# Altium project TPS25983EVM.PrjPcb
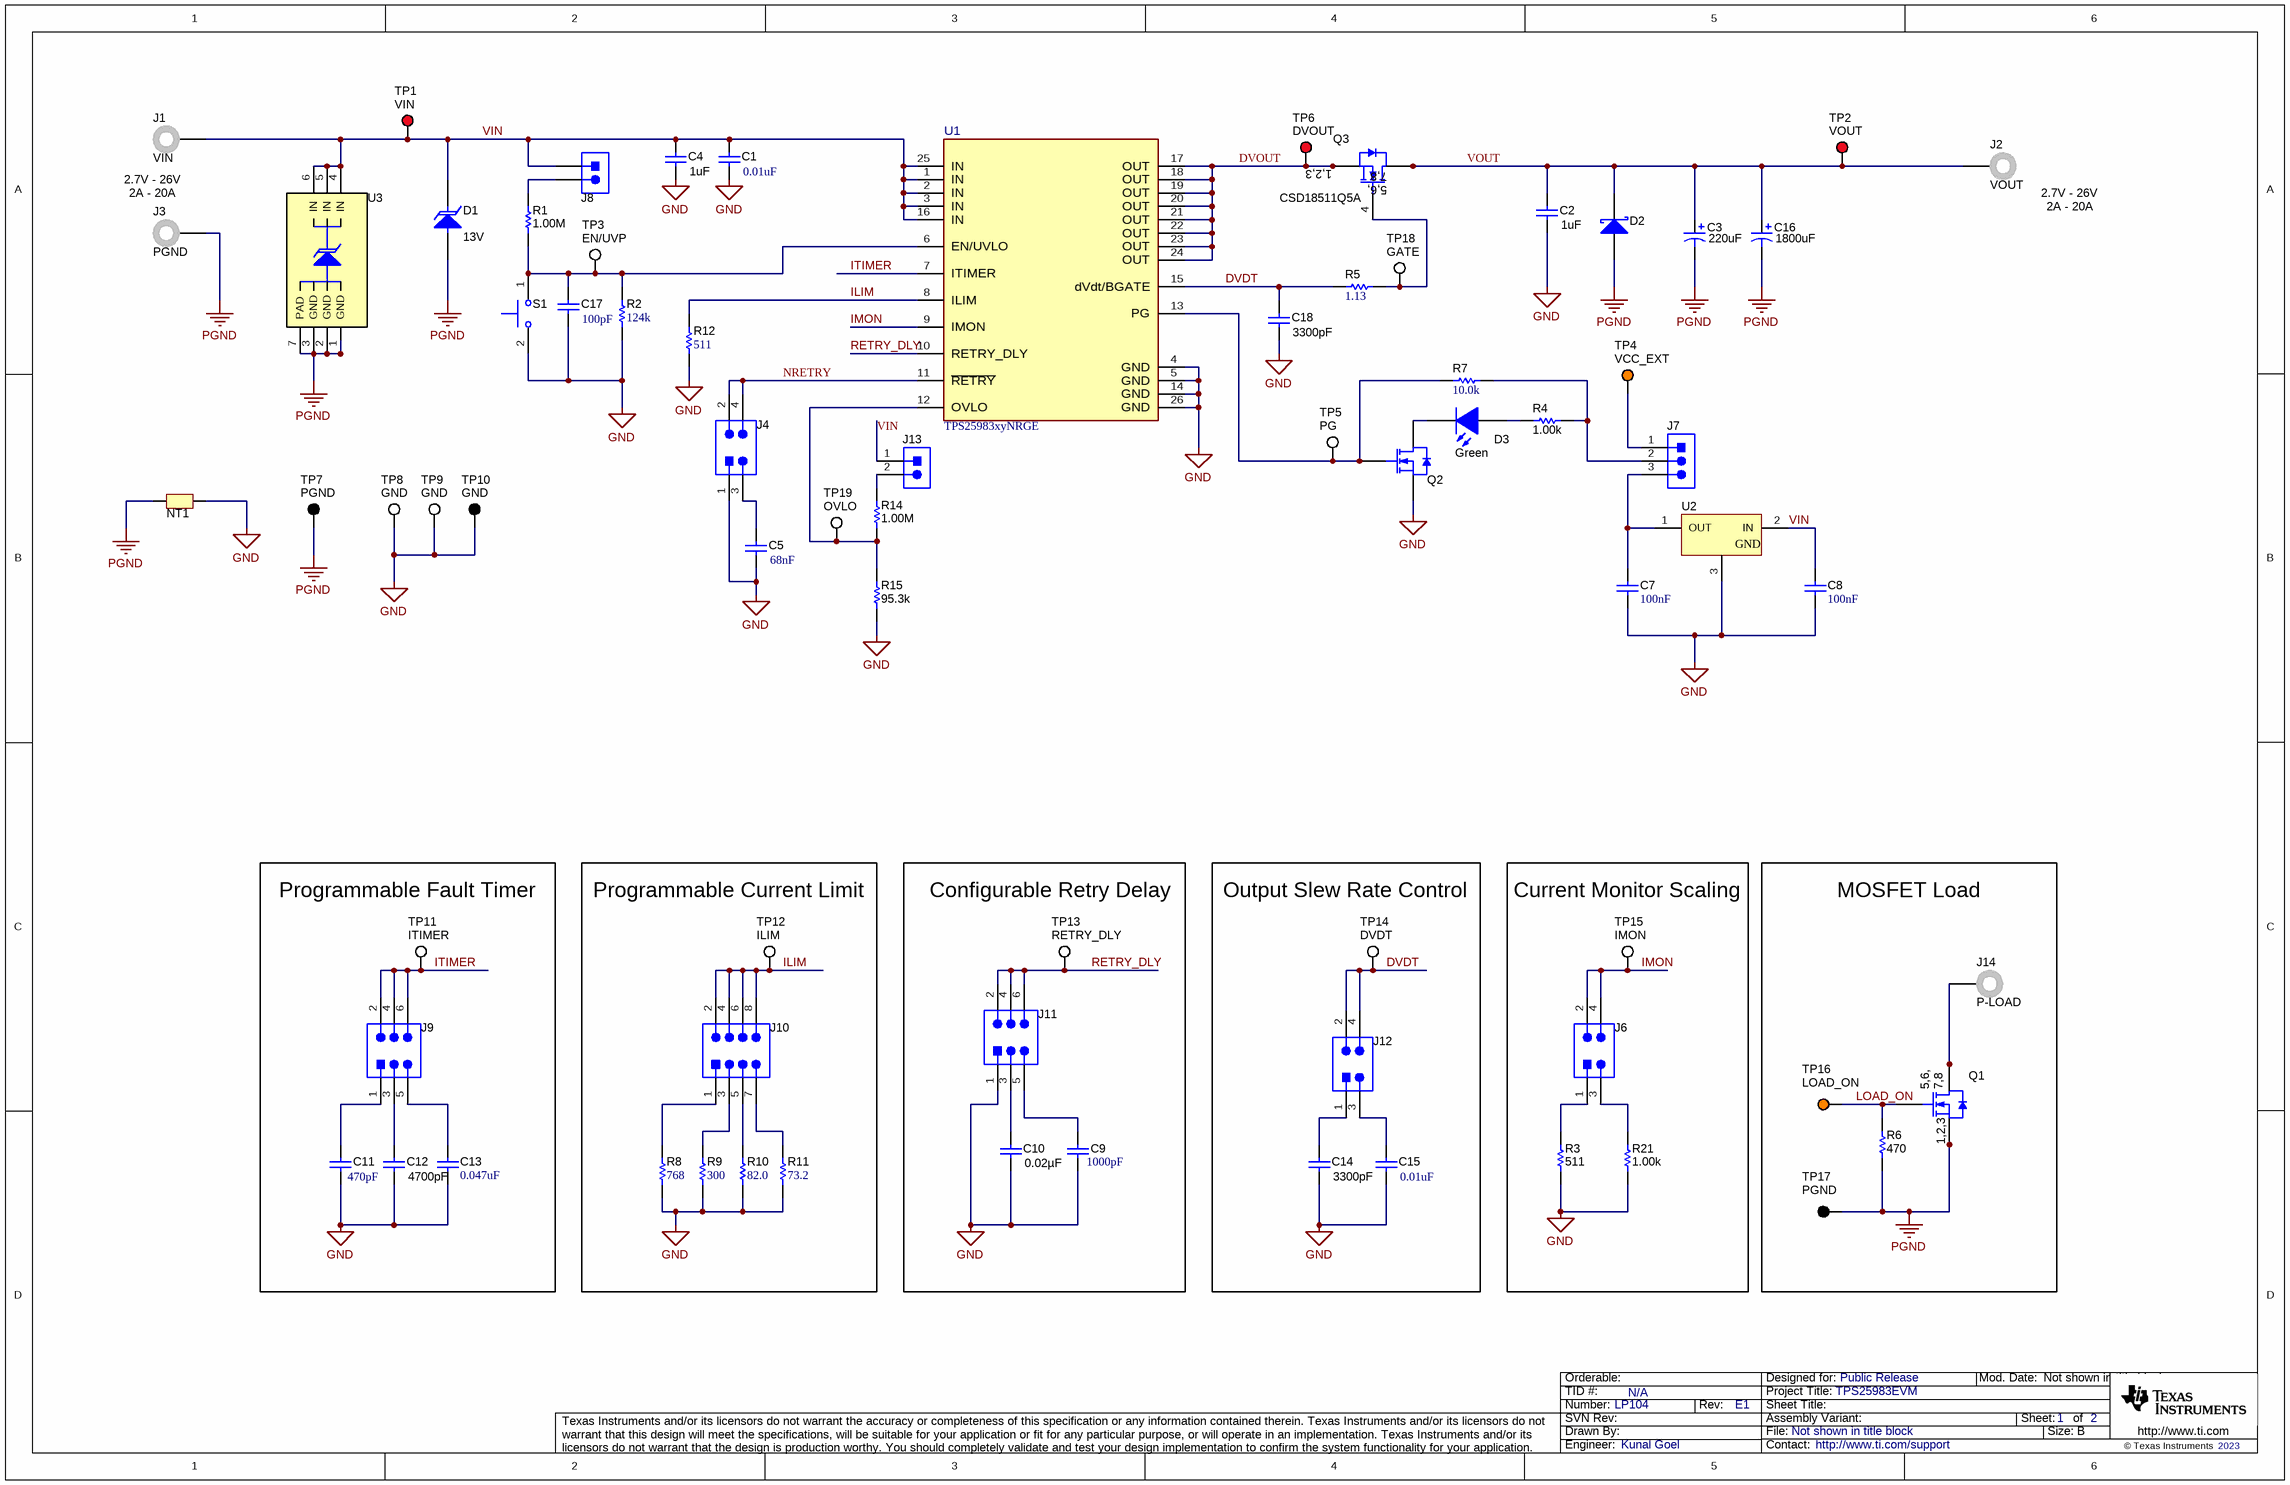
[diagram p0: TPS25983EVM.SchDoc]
CopyrightYear: 2023; PCB_Layout: Pactron; PCB_Rev: E1; PRJ_Customer: Public Release; PRJ_Engineer: Kunal Goel; PRJ_Number: LP104; PRJ_Title: TPS25983EVM; SCH_Rev: E1; TechSupport: http://www.ti.com/support; TID: N/A
2 sheets, 100 parts. Net scope: global (net labels, ports and power ports of the same name join across sheets).
Board file: TPS25983EVM_060523-1m.PcbDoc
Sheets:
  TPS25983EVM.SchDoc
  TPS25983EVM_Hardware.SchDoc

## Sheet TPS25983EVM.SchDoc
size 431 x 279 mm; Date: Not shown in title block; ApprovedBy: Not shown in title block; CheckedBy: Not shown in title block; Author: Not shown in title block; CompanyName: Not shown in title block; Engineer: Not shown in title block; Organization: Not shown in title block; Address1: Not shown in title block; Address2: Not shown in title block; Address3: Not shown in title block; Address4: Not shown in title block; DocumentNumber: 1; Revision: Use project parameter SCH_Rev; SheetNumber: 1; SheetTotal: 2

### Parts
C1  ValueDisplayed: 0.01uF  [0603]  (hidden comment: C0603C103J5RACTU)
C2  ValueDisplayed: 1uF  [0805_HV]  (hidden comment: GMK212B7105KG-T)
C3  ValueDisplayed: 220uF  [SM_RADIAL_G]  (hidden comment: EEE-FC1V221P)
C4  ValueDisplayed: 1uF  [0805_HV]  (hidden comment: GMK212B7105KG-T)
C5  Cap_F: 68nF  [0603]  (hidden comment: 885012206070)
C7  Cap_F: 100nF  [0603]  (hidden comment: 06035C104KAT2A)
C8  Cap_F: 100nF  [0603]  (hidden comment: 06035C104KAT2A)
C9  ValueDisplayed: 1000pF  [0603]  (hidden comment: C0603C102K3GACTU)
C10  ValueDisplayed: 0.02µF  [0805_HV]  (hidden comment: GRM21B5C1H203JA01L)
C11  ValueDisplayed: 470pF  [0603]  (hidden comment: 06035A471JAT2A)
C12  ValueDisplayed: 4700pF  [0603]  (hidden comment: C0603C472J5RACTU)
C13  ValueDisplayed: 0.047uF  [0603]  (hidden comment: C1608X7S2A473K080AB)
C14  ValueDisplayed: 3300pF  [0603]  (hidden comment: C0603X332K5RACTU)
C15  ValueDisplayed: 0.01uF  [0603]  (hidden comment: GRM1885C1H103JA01D)
C16  ValueDisplayed: 1800uF  [PW_1800x2000]  (hidden comment: UPW1V182MHD6)
C17  ValueDisplayed: 100pF  [0603]  (hidden comment: 885012006057)
C18  ValueDisplayed: 3300pF  [0603]  (hidden comment: C0603X332K5RACTU)
D1  value 13V  [SMC]  (hidden comment: SMCJ13A-TR)
D2  B530C-13-F  [SMC]  (value not drawn)
D3  value Green  [LTST-C170KGKT_Green]  (hidden comment: LTST-C170KGKT)
J1  VIN  [Keystone575-8]
J2  VOUT  [Keystone575-8]
J3  PGND  [Keystone575-8]
J4  PEC02DAAN  [Sullins_PEC02DAAN]  (value not drawn)
J6  PEC02DAAN  [Sullins_PEC02DAAN]  (value not drawn)
J7  Header_3x1_Launchpad  [CONN_PEC03SAAN]  (value not drawn)
J8  Header_2x1  [Sullins_PBC02SAAN]  (value not drawn)
J9  PEC03DAAN  [SULLINS_PEC03DAAN]  (value not drawn)
J10  PEC04DAAN  [CONN_PEC04DAAN]  (value not drawn)
J11  PEC03DAAN  [SULLINS_PEC03DAAN]  (value not drawn)
J12  PEC02DAAN  [Sullins_PEC02DAAN]  (value not drawn)
J13  PEC02SAAN  [CONN_PEC02SAAN]  (value not drawn)
J14  P-LOAD  [Keystone575-8]
NT1  Net-Tie  [NetTie_0603]  (value not drawn)  (net tie, no BOM)
Q1  CSD17573Q5B  [DNK0008A]  (value not drawn)
Q2  2N7002  [SOT-23]  (value not drawn)
Q3  CSD18511Q5A  [DQJ0008A]
R1  ValueDisplayed: 1.00M  [0603]  (hidden comment: RC0603FR-071ML)
R2  ValueDisplayed: 124k  [0603]  (hidden comment: CRCW0603124KFKEA)
R3  ValueDisplayed: 511  [0603]  (hidden comment: RC0603FR-07511RL)
R4  ValueDisplayed: 1.00k  [0603]  (hidden comment: RC0603FR-071KL)
R5  ValueDisplayed: 1.13  [0805_HV]  (hidden comment: CRCW08051R13FKEA)
R6  ValueDisplayed: 470  [0603]  (hidden comment: RC0603FR-07470RL)
R7  ValueDisplayed: 10.0k  [0603]  (hidden comment: RG1608P-103-B-T5)
R8  ValueDisplayed: 768  [0603]  (hidden comment: RC0603FR-07768RL)
R9  ValueDisplayed: 300  [0603]  (hidden comment: RC0603FR-07300RL)
R10  ValueDisplayed: 82.0  [0603]  (hidden comment: RC0603FR-0782RL)
R11  ValueDisplayed: 73.2  [0603]  (hidden comment: RC0603FR-0773R2L)
R12  ValueDisplayed: 511  [0603]  (hidden comment: RT0603BRD07511RL)
R14  ValueDisplayed: 1.00M  [0603]  (hidden comment: RC0603FR-071ML)
R15  ValueDisplayed: 95.3k  [0603]  (hidden comment: RC0603FR-0795K3L)
R21  ValueDisplayed: 1.00k  [0603]  (hidden comment: RC0603FR-071KL)
S1  SKRKAEE020  [SW_SKRKAE]  (value not drawn)
TP1  VIN  [Keystone5010]
TP2  VOUT  [Keystone5010]
TP3  EN/UVP  [Keystone5012]
TP4  VCC_EXT  [Keystone5013]
TP5  PG  [Keystone5012]
TP6  DVOUT  [Keystone5010]
TP7  PGND  [Keystone5011]
TP8  GND  [Testpoint_Keystone_Compact]
TP9  GND  [Testpoint_Keystone_Compact]
TP10  GND  [Keystone5011]
TP11  ITIMER  [Keystone5012]
TP12  ILIM  [Keystone5012]
TP13  RETRY_DLY  [Keystone5012]
TP14  DVDT  [Keystone5012]
TP15  IMON  [Keystone5012]
TP16  LOAD_ON  [Keystone5013]
TP17  PGND  [Keystone5011]
TP18  GATE  [Keystone5012]
TP19  OVLO  [Keystone5012]
U1  TPS25983xyNRGE  [RGE0024M-MFG]
U2  LM3480IM3-3.3/NOPB  [DBZ0003A_N]  (value not drawn)
U3  TVS2200DRVR  [DRV0006A]  (value not drawn)

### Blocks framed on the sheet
Programmable Fault Timer: C11-C13 J9 TP11
Programmable Current Limit: J10 R8-R11 TP12
Configurable Retry Delay: C9 C10 J11 TP13
Output Slew Rate Control: C14 C15 J12 TP14
Current Monitor Scaling: J6 R3 R21 TP15
MOSFET Load: J14 Q1 R6 TP16 TP17

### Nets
GND: C1.2 C2.2 C4.2 C5.2 C7.2 C8.2 C9.2 C10.2 C11.2 C12.2 C13.2 C14.2 C15.2 C17.2 C18.2 J4.1 J11.1 NT1.1 Q2.2(S) R2.1 R3.1 R8.1 R9.1 R10.1 R11.1 R12.2 R15.1 R21.1 S1.2 TP8.1 TP9.1 TP10.1 U1.4(GND) U1.5(GND) U1.14(GND) U1.26(GND) U2.3(GND)
PGND: C3.2(-) C16.2(-) D1.2(A) D2.2(A) J3.1 NT1.2 Q1.1(S) Q1.2(S) Q1.3(S) R6.1 TP7.1 TP17.1 U3.1(GND) U3.2(GND) U3.3(GND) U3.7(PAD)
DVDT: C18.1 J12.2 J12.4 R5.1 TP14.1 U1.15(dVdt/BGATE)
DVOUT: Q3.1(S) Q3.2(S) Q3.3(S) TP6.1 U1.17(OUT) U1.18(OUT) U1.19(OUT) U1.20(OUT) U1.21(OUT) U1.22(OUT) U1.23(OUT) U1.24(OUT)
ILIM: J10.2 J10.4 J10.6 J10.8 R12.1 TP12.1 U1.8(ILIM)
IMON: J6.2 J6.4 TP15.1 U1.9(IMON)
ITIMER: J9.2 J9.4 J9.6 TP11.1 U1.7(ITIMER)
LOAD_ON: Q1.4(G) R6.2 TP16.1
NRETRY: J4.2 J4.4 U1.11(~{RETRY})
RETRY_DLY: J11.2 J11.4 J11.6 TP13.1 U1.10(RETRY_DLY)
VIN: C1.1 C4.1 C8.1 D1.1(K) J1.1 J8.1 J13.1 TP1.1 U1.1(IN) U1.2(IN) U1.3(IN) U1.16(IN) U1.25(IN) U2.2(IN) U3.4(IN) U3.5(IN) U3.6(IN)
VOUT: C2.1 C3.1(+) C16.1(+) D2.1(K) J2.1 Q3.5(D) Q3.6(D) Q3.7(D) Q3.8(D) Q3.9(D) TP2.1
NetC5_1: C5.1 J4.3
NetC7_1: C7.1 J7.3 U2.1(OUT)
NetC9_1: C9.1 J11.5
NetC10_1: C10.1 J11.3
NetC11_1: C11.1 J9.1
NetC12_1: C12.1 J9.3
NetC13_1: C13.1 J9.5
NetC14_1: C14.1 J12.1
NetC15_1: C15.1 J12.3
NetC17_1: C17.1 R1.1 R2.2 S1.1 TP3.1 U1.6(EN/UVLO)
NetD3_1: D3.1(A) R4.2
NetD3_2: D3.2(K) Q2.3(D)
NetJ6_1: J6.1 R3.2
NetJ6_3: J6.3 R21.2
NetJ7_1: J7.1 TP4.1
NetJ7_2: J7.2 R4.1 R7.2
NetJ8_2: J8.2 R1.2
NetJ10_1: J10.1 R8.2
NetJ10_3: J10.3 R9.2
NetJ10_5: J10.5 R10.2
NetJ10_7: J10.7 R11.2
NetJ13_2: J13.2 R14.2
NetJ14_1: J14.1 Q1.5(D) Q1.6(D) Q1.7(D) Q1.8(D) Q1.9(D)
NetQ2_1: Q2.1(G) R7.1 TP5.1 U1.13(PG)
NetQ3_4: Q3.4(G) R5.2 TP18.1
NetR14_1: R14.1 R15.2 TP19.1 U1.12(OVLO)

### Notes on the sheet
- 2.7V - 26V
- 2A - 20A

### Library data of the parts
C1 = CMP-0006850-4: CAP, CERM, 0.01 uF, 50 V, +/- 5%, X7R, 0603; Manufacturer: Kemet; TaMin_C: -55°C; Polarized: N; SizeAreaWB_mm2: 4.68; Value1: Unknown; U/M: EA; Value: 0.01uF; TaMax_C: 125°C; SizeZ_mm: 1; SizeX_mm: 1.6; SizeY_mm: 0.8; Value2: 50V; SizeArea_mm2: 1.28; Cap_F: 10nF; AEC Category: Q200
C2 C4 = CMP-0008024-2: CAP, CERM, 1 uF, 35 V, +/- 10%, X7R, 0805; Manufacturer: Taiyo Yuden; TaMin_C: -55°C; Polarized: N; SizeAreaWB_mm2: 6.75; Value1: Unknown; U/M: EA; Value: 1uF; TaMax_C: 125°C; SizeZ_mm: 1.45; SizeX_mm: 2; SizeY_mm: 1.25; Cap_Case: 0805; Value2: 35V; SizeArea_mm2: 2.5; CompType: Capacitor; Cap_F: 1µF; AEC Category: Q200
C3 = CMP-0010667-1: CAP, AL, 220 uF, 35 V, +/- 20%, 0.15 ohm, SMD; Manufacturer: Panasonic; TaMin_C: -40°C; ESR_ohm: 1.5d; Polarized: Y; SizeAreaWB_mm2: 172.2; U/M: EA; Value: 220uF; TaMax_C: 105°C; SizeZ_mm: 10.2; SizeX_mm: 12; SizeY_mm: 10.3; Cap_Case: G; Value2: 35V; SizeArea_mm2: 123.6; CompType: Capacitor; Cap_F: 220µF; IRMS_A: 6.7dA; AEC Category: Q200
C5 = CMP-0750069-1: CAP, CERM, 0.068 µF, 25 V,+/- 10%, X7R, 0603; Manufacturer: Wurth Elektronik; SizeAreaWB_mm2: 4.68; U/M: EA; SizeArea_mm2: 1.28; TaMin_C: -55°C; Value: 0.068uF; SizeY_mm: 0.8; SizeX_mm: 1.6; AEC Category: Q200; VDC_V: 25V; AEC Qualified: N; SizeZ_mm: 1; TaMax_C: 125°C
C7 C8 = CMP-0006802-4: CAP, CERM, 0.1 uF, 50 V, +/- 10%, X7R, 0603; Manufacturer: AVX; TaMin_C: -55°C; Polarized: N; SizeAreaWB_mm2: 4.68; Value1: Unknown; U/M: EA; Value: 0.1uF; TaMax_C: 125°C; SizeZ_mm: 1; SizeX_mm: 1.6; SizeY_mm: 0.8; Value2: 50V; SizeArea_mm2: 1.28; AEC Category: Q200
C9 = CMP-0006846-4: CAP, CERM, 1000 pF, 25 V, +/- 10%, C0G/NP0, 0603; Manufacturer: Kemet; TaMin_C: -55°C; ESR_ohm: 0; Polarized: N; SizeAreaWB_mm2: 4.68; Value1: 0 ohm; U/M: EA; Value: 1000pF; TaMax_C: 125°C; SizeZ_mm: 1; SizeX_mm: 1.6; SizeY_mm: 0.8; Value2: 25V; SizeArea_mm2: 1.28; Cap_F: 1nF; IRMS_A: 0A; AEC Category: Q200
C10 = CMP-0080095-1: CAP, CERM, 0.02 µF, 50 V,+/- 5%, C0G/NP0, 0805; Manufacturer: MuRata; Cap_F: 20nF; SizeAreaWB_mm2: 6.75; SizeArea_mm2: 2.5; AEC Qualified: N; AEC Category: Q200; Value: 0.02uF; TaMax_C: 125°C; SizeZ_mm: 1.45; TaMin_C: -55°C; VDC_V: 50V; SizeY_mm: 1.25; U/M: EA; CompType: Capacitor; SizeX_mm: 2; Cap_Case: 0805
C11 = CMP-0006790-4: CAP, CERM, 470 pF, 50 V, +/- 5%, C0G/NP0, 0603; Manufacturer: AVX; TaMin_C: -55°C; ESR_ohm: 0.063; Polarized: N; SizeAreaWB_mm2: 4.68; Value1: 0.063 ohm; U/M: EA; Value: 470pF; TaMax_C: 125°C; SizeZ_mm: 1; SizeX_mm: 1.6; SizeY_mm: 0.8; Value2: 50V; SizeArea_mm2: 1.28; AEC Category: Q200
C12 = CMP-0006942-4: CAP, CERM, 4700 pF, 50 V, +/- 5%, X7R, 0603; Manufacturer: Kemet; TaMin_C: -55°C; Polarized: N; SizeAreaWB_mm2: 4.68; Value1: Unknown; U/M: EA; Value: 4700pF; TaMax_C: 125°C; SizeZ_mm: 1; SizeX_mm: 1.6; SizeY_mm: 0.8; Value2: 50V; SizeArea_mm2: 1.28; CompType: Capacitor; Cap_F: 4.7nF; AEC Category: Q200
C13 = CMP-0007060-4: CAP, CERM, 0.047 uF, 100 V, +/- 10%, X7S, 0603; Manufacturer: TDK; TaMin_C: -55°C; ESR_ohm: 0.089796; Polarized: N; SizeAreaWB_mm2: 4.68; Value1: 0.089796 ohm; U/M: EA; TaMax_C: 125°C; SizeZ_mm: 1; SizeX_mm: 1.6; SizeY_mm: 0.8; Value2: 100V; SizeArea_mm2: 1.28; CompType: Capacitor; Cap_F: 47nF; IRMS_A: 5.67484dA; AEC Category: Q200
C14 C18 = CMP-0006985-4: CAP, CERM, 3300 pF, 50 V, +/- 10%, X7R, 0603; Manufacturer: Kemet; TaMin_C: -55°C; Polarized: N; SizeAreaWB_mm2: 4.68; Value1: Unknown; U/M: EA; Value: 3300pF; TaMax_C: 125°C; SizeZ_mm: 1; SizeX_mm: 1.6; SizeY_mm: 0.8; Value2: 50V; SizeArea_mm2: 1.28; CompType: Capacitor; Cap_F: 3.3nF; AEC Category: Q200
C15 = CMP-0007174-4: CAP, CERM, 0.01 uF, 50 V, +/- 5%, C0G/NP0, 0603; Manufacturer: MuRata; TaMin_C: -55°C; Polarized: N; SizeAreaWB_mm2: 4.68; Value1: Unknown; U/M: EA; Value: 0.01uF; TaMax_C: 125°C; SizeZ_mm: 1; SizeX_mm: 1.6; SizeY_mm: 0.8; Value2: 50V; SizeArea_mm2: 1.28; Cap_F: 10nF; AEC Category: Q200
C16 = CMP-0010552-2: CAP, AL, 1800 uF, 35 V, +/- 20%, 0.028 ohm, TH; Manufacturer: Nichicon; TaMin_C: -55°C; ESR_ohm: 0.028; Polarized: Y; SizeAreaWB_mm2: 400; U/M: EA; Value: 1800uF; TaMax_C: 105°C; SizeZ_mm: 22; SizeX_mm: 18; Cap_Case: 18x20mm; Value2: 35V; SizeArea_mm2: 324; CompType: Capacitor; AEC Qualified: N; Cap_F: 1.8mF; IRMS_A: 2.49A; AEC Category: Q200
C17 = CMP-0006822-4: CAP, CERM, 100 pF, 50 V, +/- 5%, C0G/NP0, 0603; Manufacturer: Wurth Elektronik; TaMin_C: -55°C; Polarized: N; SizeAreaWB_mm2: 4.68; Value1: Unknown; U/M: EA; Value: 100pF; TaMax_C: 125°C; SizeZ_mm: 1; SizeX_mm: 1.6; SizeY_mm: 0.8; Value2: 50V; SizeArea_mm2: 1.28; CompType: Capacitor; AEC Category: Q200
D1 = CMP-0085423-1: Diode, TVS, Uni, 13 V, 21.5 Vc, 1500 W, 73 A, SMC; Manufacturer: STMicroelectronics; SizeAreaWB_mm2: 83.2686; SizeZ_mm: 2.62; SizeY_mm: 6.22; Ipp: 73A; Ppk: 1.5kW; RJA_CperW: 90; SizeArea_mm2: 50.5686; SizeX_mm: 8.13; Value1: 21.5V; Vbr_Min: 14.4V; AEC Qualified: N; AEC Category: Q101
D2 = CMP-0028430-1: Diode, Schottky, 30 V, 5 A, SMC; Manufacturer: Diodes Inc.; Io_A: 5A; Green_Lifecycle: Active; SizeAreaWB_mm2: 83.2686; Vr_V: 30V; Green_REACh: Passed; TJmax_C: 125°C; U/M: EA; Value: 30V; SizeZ_mm: 2.6; SizeX_mm: 8.13; SizeY_mm: 6.22; Vf_V: 5.5dV; Value2: 0.55V; SizeArea_mm2: 50.5686; AEC Category: Q101; RJC_CperW: 10
D3 = CMP-0002888-1: LED, Green, SMD; Manufacturer: Lite-On; Type: AlInGaP; Vf_V: 2V; Io_A: 20mA; Value1: W; U/M: EA
J1-J3 J14 = CMP-0055166-2: Standard Banana Jack, Uninsulated, 8.9mm; Manufacturer: Keystone; PartNumber: 575-8; CT: TRUE; Green_REACh: Passed; CNHeader: FALSE; Green_Lifecycle: Active
J4 J6 J12 = CMP-0054558-1: Header, 100mil, 2x2, Tin, TH; Manufacturer: Sullins Connector Solutions; CNHeader: TRUE; Green_Lifecycle: Not Set; Green_REACh: Incomplete; CT: FALSE
J7 = CMP-0002338-1: Header, 100mil, 3x1, Tin, TH; PartNumber: PEC03SAAN; Manufacturer: Sullins Connector Solutions; Cert_UL: Y; CNHeader: TRUE; CT: FALSE; Current_A: 3A; Gender: Male; Green_Lifecycle: Not Set; Green_REACh: Incomplete; Pitch_mm: 2.54; Row_Count: 1; Shrouded: N; Voltage_V: 1.8kV
J8 = CMP-0054566-1: Header, 100mil, 2x1, Gold, TH; PartNumber: PBC02SAAN; Manufacturer: Sullins Connector Solutions; Pitch_mm: 2.54; Gender: Male; Shrouded: N; Row_Count: 1; Current_A: 3A; Voltage_V: 1.8kV; Cert_UL: Y; CNHeader: TRUE; CT: FALSE; Green_Lifecycle: Active; Green_REACh: Passed
J9 J11 = CMP-0054552-1: Header, 100mil, 3x2, Tin, TH; Manufacturer: Sullins Connector Solutions; CNHeader: TRUE; Current_A: 3A; Green_Lifecycle: Not Set; Shrouded: N; Gender: Male; Green_REACh: Incomplete; Voltage_V: 1.8kV; Row_Count: 2; RowSpacing_mm: 2.54; CT: FALSE; Cert_UL: Y
J10 = CMP-0054542-1: Header, 100mil, 4x2, Tin, TH; Manufacturer: Sullins Connector Solutions; CNHeader: TRUE; Current_A: 3A; Green_Lifecycle: Not Set; Shrouded: N; Gender: Male; Green_REACh: Incomplete; Voltage_V: 1.8kV; Row_Count: 2; RowSpacing_mm: 2.54; CT: FALSE; Cert_UL: Y
J13 = CMP-0002337-1: Header, 100mil, 2x1, Tin, TH; Manufacturer: Sullins Connector Solutions; CNHeader: TRUE; Current_A: 3A; Green_Lifecycle: Not Set; Shrouded: N; Gender: Male; Green_REACh: Incomplete; Voltage_V: 1.8kV; Row_Count: 1; Pitch_mm: 2.54; CT: FALSE; Cert_UL: Y
NT1 = CMP-0078142-3: Single point connection between nets.
Q1 = CMP-0000586-2: MOSFET, N-CH, 30 V, 100 A, DNK0008A (VSON-CLIP-8); Manufacturer: Texas Instruments; SizeZ_mm: 1; ChType: N; Value2: 49 nC; Value1: 0.0014; VdsMax_V: 30V; SizeX_mm: 6; SizeY_mm: 5; Vgs_V: 20V; Value: 30V; Rdson45_ohm: 1.45m; SizeArea_mm2: 30; AEC Category: Q101; IdsMax_A: 100A; SizeAreaWB_mm2: 56; U/M: EA; QgTyp_nC: 49
Q2 = CMP-0000768-1: MOSFET, N-CH, 60 V, 115 A, SOT-23; Manufacturer: Fairchild Semiconductor; SizeZ_mm: 1.1; ChType: N; VdsMax_V: 60V; SizeX_mm: 2.5; SizeY_mm: 3; Vgs_V: 20V; Value: 60V; SizeArea_mm2: 7.5; AEC Category: Q101; IdsMax_A: 115A; SizeAreaWB_mm2: 14; U/M: EA
Q3 = CMP-0000711-1: MOSFET, N-CH, 40 V, 100 A, DQJ0008A (VSONP-8); Alternate Manufacturer: None; Manufacturer: Texas Instruments; SizeZ_mm: 1.1; ChType: N; Value2: 63 nC; Value1: 0.003; VdsMax_V: 40V; SizeX_mm: 6; SizeY_mm: 4.9; Vgs_V: 20V; Value: 40V; Rdson45_ohm: 3.5m; SizeArea_mm2: 29.4; AEC Category: Q101; IdsMax_A: 100A; SizeAreaWB_mm2: 55.2; U/M: EA; QgTyp_nC: 63
R1 R14 = CMP-0022899-2: RES, 1.00 M, 1%, 0.1 W, 0603; Manufacturer: Yageo America; Power_W: 100mW; TempCo: 200 ppm/C; Value_Code: 1M00; U/M: EA; Value: 1.00Meg; EIA_Code: E96; Res_ohm: 1M; SizeX_mm: 1.6; SizeY_mm: 0.8; SizeZ_mm: 1; Value2: 0.1W; SizeArea_mm2: 1.28; CompType: Resistor; VDC_V: 150V; AEC Category: Q200
R2 = CMP-0022026-4: RES, 124 k, 1%, 0.1 W, AEC-Q200 Grade 0, 0603; Manufacturer: Vishay-Dale; Power_W: 100mW; TempCo: 100 ppm/C; Value: 124k; EIA_Code: E96; SizeX_mm: 1.6; SizeY_mm: 0.8; SizeZ_mm: 1; Value2: 0.1W; SizeArea_mm2: 1.28; AEC Qualified: Y; VDC_V: 75V; AEC Category: Q200; AEC Grade: 0
R3 = CMP-0023165-3: RES, 511, 1%, 0.1 W, 0603; Manufacturer: Yageo America; Power_W: 100mW; TempCo: 200 ppm/C; Value_Code: 511R; U/M: EA; Value: 511; EIA_Code: E96; SizeX_mm: 1.6; SizeY_mm: 0.8; SizeZ_mm: 1; Value2: 0.1W; SizeArea_mm2: 1.28; VDC_V: 150V; AEC Category: Q200
R4 = CMP-0022895-3: RES, 1.00 k, 1%, 0.1 W, 0603; Manufacturer: Yageo America; Power_W: 100mW; TempCo: 200 ppm/C; Value_Code: 1k00; U/M: EA; Value: 1.00k; EIA_Code: E96; Res_ohm: 1k; SizeX_mm: 1.6; SizeY_mm: 0.8; SizeZ_mm: 1; Value2: 0.1W; SizeArea_mm2: 1.28; CompType: Resistor; VDC_V: 150V; AEC Category: Q200
R5 = CMP-0021014-3: RES, 1.13, 1%, 0.125 W, AEC-Q200 Grade 0, 0805; Manufacturer: Vishay-Dale; Power_W: 125mW; TempCo: 100 ppm/C; Value_Code: 1R13; Value: 1.13; EIA_Code: E96; SizeX_mm: 2; SizeY_mm: 1.25; SizeZ_mm: 1.45; Value2: 0.125W; SizeArea_mm2: 2.5; AEC Qualified: Y; VDC_V: 150V; AEC Category: Q200; AEC Grade: 0
R6 = CMP-0023129-3: RES, 470, 1%, 0.1 W, 0603; Manufacturer: Yageo America; Power_W: 100mW; TempCo: 200 ppm/C; Value_Code: 470R; U/M: EA; Value: 470; SizeX_mm: 1.6; SizeY_mm: 0.8; SizeZ_mm: 1; Value2: 0.1W; SizeArea_mm2: 1.28; VDC_V: 150V; AEC Category: Q200
R7 = CMP-0023404-3: RES, 10.0 k, 0.1%, 0.1 W, 0603; Manufacturer: Susumu Co Ltd; Power_W: 100mW; TempCo: 25 ppm/C; Value_Code: 10k0; U/M: EA; Value: 10.0k; EIA_Code: E192; Res_ohm: 10k; SizeX_mm: 1.6; SizeY_mm: 0.8; SizeZ_mm: 1; Value2: 0.1W; SizeArea_mm2: 1.28; CompType: Resistor; VDC_V: 75V; AEC Category: Q200
R8 = CMP-0023270-5: RES, 768, 1%, 0.1 W, 0603; Manufacturer: Yageo; Power_W: 100mW; TempCo: 100 ppm/C; Value_Code: 768R; Value: 768; EIA_Code: E96; SizeX_mm: 1.6; SizeY_mm: 0.8; SizeZ_mm: 1; Value2: 0.1W; SizeArea_mm2: 1.28; AEC Qualified: N; VDC_V: 75V; AEC Category: Q200; SizeAreaWB_mm2: 4.68
R9 = CMP-0023013-5: RES, 300, 1%, 0.1 W, 0603; Manufacturer: Yageo; Power_W: 100mW; TempCo: 100 ppm/C; Value_Code: 300R; Value: 300; SizeX_mm: 1.6; SizeY_mm: 0.8; SizeZ_mm: 1; Value2: 0.1W; SizeArea_mm2: 1.28; AEC Qualified: N; VDC_V: 75V; AEC Category: Q200; SizeAreaWB_mm2: 4.68
R10 = CMP-0023294-5: RES, 82.0, 1%, 0.1 W, 0603; Manufacturer: Yageo; Power_W: 100mW; TempCo: 100 ppm/C; Value_Code: 82R0; Value: 82.0; Res_ohm: 82; SizeX_mm: 1.6; SizeY_mm: 0.8; SizeZ_mm: 1; Value2: 0.1W; SizeArea_mm2: 1.28; AEC Qualified: N; VDC_V: 75V; AEC Category: Q200; SizeAreaWB_mm2: 4.68
R11 = CMP-0023264-5: RES, 73.2, 1%, 0.1 W, 0603; Manufacturer: Yageo; Power_W: 100mW; TempCo: 100 ppm/C; Value_Code: 73R2; Value: 73.2; EIA_Code: E96; SizeX_mm: 1.6; SizeY_mm: 0.8; SizeZ_mm: 1; Value2: 0.1W; SizeArea_mm2: 1.28; AEC Qualified: N; VDC_V: 75V; AEC Category: Q200; SizeAreaWB_mm2: 4.68
R12 = CMP-0024310-2: RES, 511, 0.1%, 0.1 W, 0603; Manufacturer: Yageo America; Power_W: 100mW; TempCo: 25 ppm/C; Value_Code: 511R; U/M: EA; Value: 511; EIA_Code: E192; SizeX_mm: 1.6; SizeY_mm: 0.8; SizeZ_mm: 1; Value2: 0.1W; SizeArea_mm2: 1.28; VDC_V: 75V; AEC Category: Q200
R15 = CMP-0023326-5: RES, 95.3 k, 1%, 0.1 W, 0603; Manufacturer: Yageo; Power_W: 100mW; TempCo: 100 ppm/C; Value_Code: 95k3; Value: 95.3k; EIA_Code: E96; SizeX_mm: 1.6; SizeY_mm: 0.8; SizeZ_mm: 1; Value2: 0.1W; SizeArea_mm2: 1.28; AEC Qualified: N; VDC_V: 75V; AEC Category: Q200; SizeAreaWB_mm2: 4.68
R21 = CMP-0022895-3: RES, 1.00 k, 1%, 0.1 W, 0603; Manufacturer: Yageo America; Power_W: 100mW; TempCo: 200 ppm/C; Value_Code: 1k00; U/M: EA; Value: 1.00k; EIA_Code: E96; Res_ohm: 1k; SizeX_mm: 1.6; SizeY_mm: 0.8; SizeZ_mm: 1; Value2: 0.1W; SizeArea_mm2: 1.28; VDC_V: 150V; AEC Category: Q200
S1 = CMP-0085606-1: Switch, SPST-NO, 0.05 A, 12 VDC, SMT; Manufacturer: Alps; SizeX_mm: 4.8; SizeZ_mm: 2.2; SizeArea_mm2: 13.92; SizeY_mm: 2.9; PositionCount: 1; SizeAreaWB_mm2: 22.62; VDC_V: 12V; CurrentRating_mA: 50A
TP1 TP2 TP6 = CMP-0055147-1: Test Point, Multipurpose, Red, TH; Manufacturer: Keystone; PartNumber: 5010; CNHeader: FALSE; Green_Lifecycle: Active; Green_REACh: Passed; ContactFinish: Silver; CT: TRUE
TP3 TP5 TP11-TP15 TP18 TP19 = CMP-0055149-1: Test Point, Multipurpose, White, TH; Manufacturer: Keystone; PartNumber: 5012; CNHeader: FALSE; Green_Lifecycle: Active; Green_REACh: Passed; ContactFinish: Silver; CT: TRUE
TP4 = CMP-0055150-1: Test Point, Multipurpose, Orange, TH; Manufacturer: Keystone; PartNumber: 5013; CNHeader: FALSE; Green_Lifecycle: Active; Green_REACh: Passed; ContactFinish: Silver; CT: TRUE
TP7 TP10 = CMP-0055148-1: Test Point, Multipurpose, Black, TH; Manufacturer: Keystone; PartNumber: 5011; CNHeader: FALSE; Green_Lifecycle: Active; Green_REACh: Passed; ContactFinish: Silver; CT: TRUE
TP8 TP9 = CMP-0055153-1: Test Point, Compact, SMT; Manufacturer: Keystone; PartNumber: 5016; CNHeader: FALSE; Green_Lifecycle: Active; Green_REACh: Passed; CT: TRUE
TP16 = CMP-0055150-1: Test Point, Multipurpose, Orange, TH; PartNumber: 5013; Manufacturer: Keystone; CNHeader: FALSE; ContactFinish: Silver; CT: TRUE; Green_Lifecycle: Active; Green_REACh: Passed
TP17 = CMP-0055148-1: Test Point, Multipurpose, Black, TH; PartNumber: 5011; Manufacturer: Keystone; CNHeader: FALSE; ContactFinish: Silver; CT: TRUE; Green_Lifecycle: Active; Green_REACh: Passed
U1 = CMP-0001573-1: TPS25983; Manufacturer: Texas Instruments; SizeZ_mm: 1mm; Standoff Height: 0mm
U2 = CMP-0071020-1: 100 mA, Quasi Low-Dropout Linear Voltage Regulator, 3-pin SOT-23, Pb-Free; Manufacturer: Texas Instruments; PowerWise: N; CompType: LDO IC; PackageTopMarking: L0A*XTT
U3 = CMP-0077834-1: 22-V Precision Surge Protection Clamp, DRV0006A (WSON-6); Alternate Manufacturer: Texas Instruments; SizeAreaWB_mm2: 9.0; SizeZ_mm: 0.8; SizeX_mm: 2.0; SizeArea_mm2: 4.0; CompType: IC; AEC Qualified: N; AEC Category: Q200

## Sheet TPS25983EVM_Hardware.SchDoc
size 431 x 279 mm; Date: Not shown in title block; ApprovedBy: Not shown in title block; CheckedBy: Not shown in title block; Author: Not shown in title block; CompanyName: Not shown in title block; Engineer: Not shown in title block; Organization: Not shown in title block; Address1: Not shown in title block; Address2: Not shown in title block; Address3: Not shown in title block; Address4: Not shown in title block; DocumentNumber: 1; Revision: Use project parameter SCH_Rev; SheetNumber: 2; SheetTotal: 2; PageSetup: Record=PageOptions¦CenterHorizontal=True¦CenterVertical=True¦PrintScale=1.00¦XCorrection=1.00¦YCorrection=1.00¦PrintKind=0¦BorderSize=5000000¦LeftOffset=0¦BottomOffset=0¦Orientation=2¦PaperLength=1000¦PaperWidth=1000¦Scale=100¦PaperSource=15¦PrintQuality=600¦MediaType=1¦DitherType=10¦PaperKind=Letter¦PrintScaleMode=1
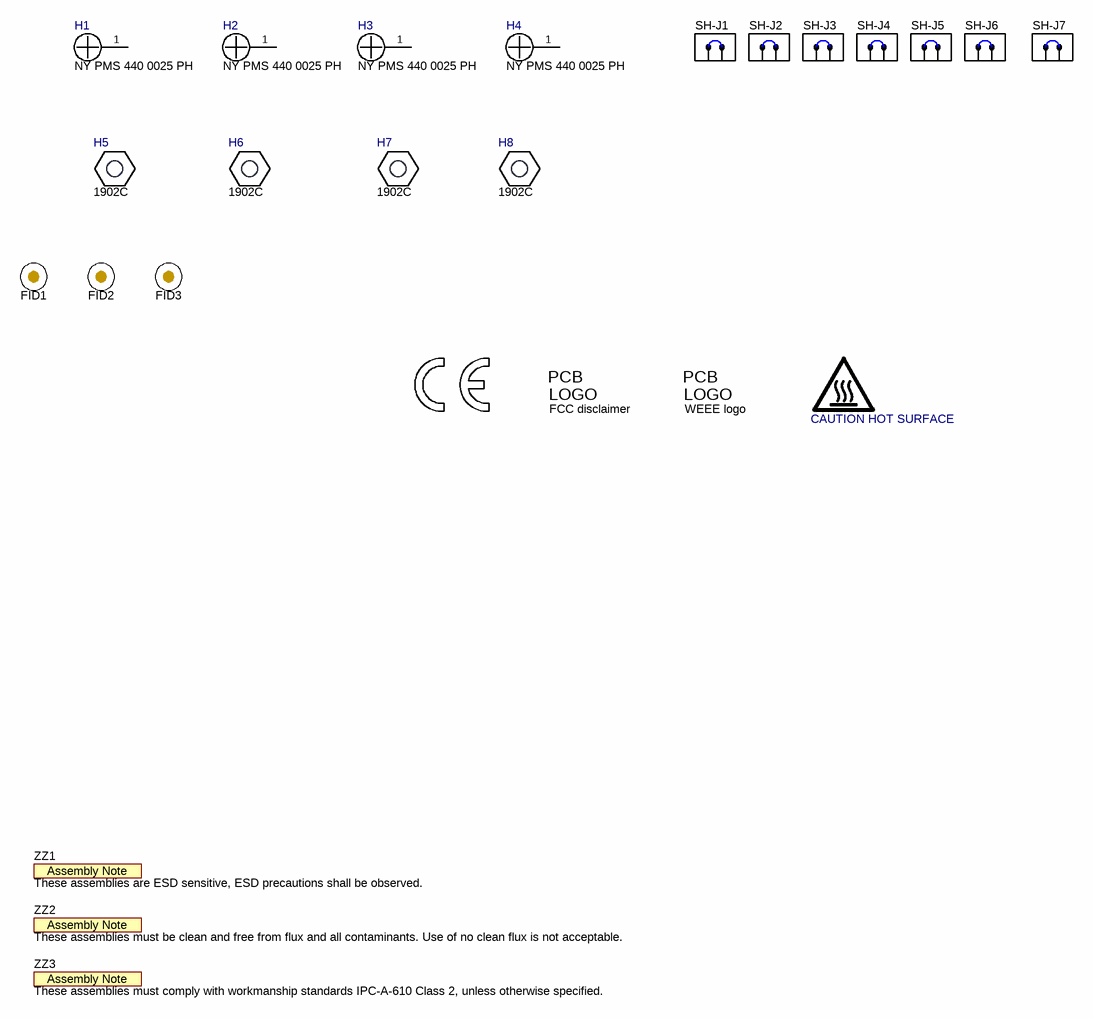
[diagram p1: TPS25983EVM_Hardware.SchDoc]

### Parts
FID1  Fiducial  [Fiducial10-20]  (value not drawn)
FID2  Fiducial  [Fiducial10-20]  (value not drawn)
FID3  Fiducial  [Fiducial10-20]  (value not drawn)
H1  NY PMS 440 0025 PH  [NY PMS 440 0025 PH]
H2  NY PMS 440 0025 PH  [NY PMS 440 0025 PH]
H3  NY PMS 440 0025 PH  [NY PMS 440 0025 PH]
H4  NY PMS 440 0025 PH  [NY PMS 440 0025 PH]
H5  1902C  [Keystone_1902C]
H6  1902C  [Keystone_1902C]
H7  1902C  [Keystone_1902C]
H8  1902C  [Keystone_1902C]
Logo1  CE Mark  [CE_Mark_5mm]  (value not drawn)  (no BOM)
Logo2  WEEE logo  [WEEE_Minimum]  (no BOM)
Logo4  FCC disclaimer  [FCC_disclaimer_stacked]  (no BOM)
Logo5  CAUTION HOT SURFACE  [IEC_HotSurface_Small]  (no BOM)
SH-J1  SNT-100-BK-G  [SNT-100-BK-G]  (value not drawn)
SH-J2  SNT-100-BK-G  [SNT-100-BK-G]  (value not drawn)
SH-J3  SNT-100-BK-G  [SNT-100-BK-G]  (value not drawn)
SH-J4  SNT-100-BK-G  [SNT-100-BK-G]  (value not drawn)
SH-J5  SNT-100-BK-G  [SNT-100-BK-G]  (value not drawn)
SH-J6  SNT-100-BK-G  [SNT-100-BK-G]  (value not drawn)
SH-J7  SNT-100-BK-G  [SNT-100-BK-G]  (value not drawn)
ZZ1  These assemblies are ESD sensitive, ESD precautions shall be observed.  [AssemblyNote]  (no BOM)
ZZ2  These assemblies must be clean and free from flux and all contaminants. Use of no clean flux is not acceptable.  [AssemblyNote]  (no BOM)
ZZ3  These assemblies must comply with workmanship standards IPC-A-610 Class 2, unless otherwise specified.  [AssemblyNote]  (no BOM)

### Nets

Not connected (* = marked no-connect by the designer): H1 1; H2 1; H3 1; H4 1

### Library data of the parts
FID1-FID3 = CMP-0077181-1: Fiducial mark.  There is nothing to buy or mount.
H1-H4 = CMP-0003617-1: Machine Screw, Round, #4-40 x 1/4, Nylon, Philips panhead; Manufacturer: B&F Fastener Supply; CompType: Hardware
H5-H8 = CMP-0003610-1: Manufacturer: Keystone; CompType: Hardware
Logo1 = CMP-0074844-1: SymbolCreator: a0412235
Logo2 = CMP-0074769-1
Logo4 = CMP-0074847-1: FCC_disclaimer; Library Reference: Logo
Logo5 = CMP-0074837-1: IEC 61010-1 Hot Surface Warning; SymbolCreator: a0412235
SH-J1-SH-J7 = CMP-0003623-1: Shunt, 100mil, Gold plated, Black; Manufacturer: Samtec; Alternate Manufacturer: 3M; Alternate PartNumber: 969102-0000-DA; Value: 1x2; Note: You can "mate" this to a header by matching the designator.  i.e. use SH-J3 for header J3
ZZ1 = CMP-0077236-1
ZZ2 = CMP-0077237-1
ZZ3 = CMP-0077238-1

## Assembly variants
001: not fitted C16 C18 FID1 FID2 FID3 R12 U?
